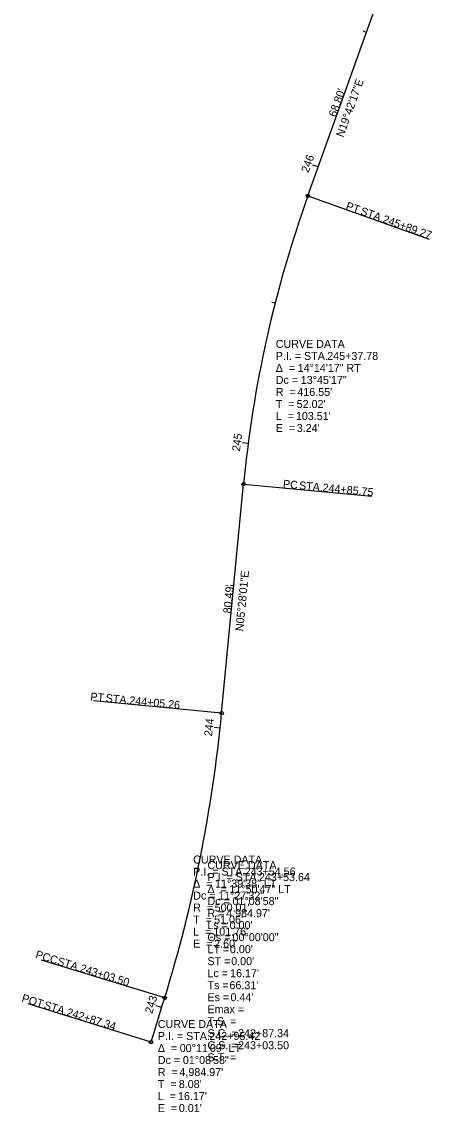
# Model space of a CAD drawing. Extents: x 2479470 to 2480226, y 287083 to 287867.
# Drawn here: x 2479991.5 to 2480134.9, y 287082.9 to 287464.3 of the extents above; entities that cross this region are included whole.
import ezdxf

# ---------------------------------------------------------------- set-up
doc = ezdxf.new("R2010")
doc.units = 0
for name, color, linetype in [('DV_X_Lot_Line', 7, 'Continuous'), ('DV_X_Property_Line', 7, 'Continuous'), ('GE_X_Alignment_100_Cardinal_Points', 7, 'Continuous'), ('GE_X_Alignment_100_Curve_Data', 7, 'Continuous'), ('GE_X_Alignment_100_Distances', 7, 'Continuous'), ('GE_X_Alignment_100_Stations', 7, 'Continuous')]:
    doc.layers.add(name, color=color, linetype=linetype)

msp = doc.modelspace()

# ---------------------------------------------------------------- linework, layer by layer
at = {"layer": 'DV_X_Lot_Line'}
for p, q in [((2480091.52, 287403.39), (2480114.72, 287468.16)), ((2480061.36, 287222.5), (2480069.02, 287302.62))]:
    msp.add_line(p, q, dxfattribs=at)
for centre, radius, start, end in [((2480483.68, 287262.94), 416.55, 160.2952, 174.5332), ((2479563.62, 287270.13), 500.01, 342.8727, 354.5332), ((2475277.55, 288590.94), 4984.97, 342.68688, 342.87268)]:
    msp.add_arc(centre, radius, start, end, dxfattribs=at)
at = {"layer": 'GE_X_Alignment_100_Cardinal_Points'}
for p, q in [((2480091.52, 287403.39), (2480133.89, 287388.22)), ((2480069.02, 287302.62), (2480113.82, 287298.34)), ((2480061.36, 287222.5), (2480016.56, 287226.79)), ((2480041.46, 287122.88), (2479998.45, 287136.14)), ((2480036.67, 287107.44), (2479993.71, 287120.83))]:
    msp.add_line(p, q, dxfattribs=at)
for centre in [(2480091.52, 287403.39), (2480069.02, 287302.62), (2480061.36, 287222.5), (2480041.46, 287122.88), (2480036.67, 287107.44)]:
    msp.add_circle(centre, 0.6, dxfattribs=at)
at = {"layer": 'GE_X_Alignment_100_Stations'}
for p, q in [((2480112, 287460.57), (2480110.87, 287460.97)), ((2480095.14, 287413.5), (2480093.26, 287414.17)), ((2480080.04, 287365.86), (2480078.88, 287366.15)), ((2480070.62, 287316.78), (2480068.64, 287317.04)), ((2480065.62, 287267.04), (2480064.42, 287267.15)), ((2480060.83, 287217.27), (2480058.84, 287217.48)), ((2480053.07, 287167.89), (2480051.89, 287168.14)), ((2480040.42, 287119.54), (2480038.51, 287120.13))]:
    msp.add_line(p, q, dxfattribs=at)

# ---------------------------------------------------------------- texts
at = {"layer": 'DV_X_Property_Line'}
for s, rotation, p in [('N19°42\'17"E', 70.2952, (2480103.89, 287423.69)), ('N05°28\'01"E', 84.5332, (2480068.91, 287251.04))]:
    msp.add_text(s, height=2.8, rotation=rotation, dxfattribs=at).set_placement(p)
at = {"layer": 'GE_X_Alignment_100_Cardinal_Points'}
for s, rotation, p in [('PT', 340.2952, (2480104.54, 287398.77)), (' STA. ', 340.2952, (2480108.64, 287397.3)), ('245+89.27', 340.2952, (2480117.41, 287394.16)), ('PC', 354.5332, (2480082.69, 287301.35)), (' STA. ', 354.5332, (2480087.27, 287300.92)), ('244+85.75', 354.5332, (2480096.55, 287300.03)), ('PT', 354.5332, (2480015.37, 287226.94)), (' STA. ', 354.5332, (2480019.7, 287226.52)), ('244+05.26', 354.5332, (2480028.98, 287225.63)), ('PCC', 342.8727, (2479996.06, 287136.91)), (' STA. ', 342.8727, (2480002.71, 287134.86)), ('243+03.50', 342.8727, (2480011.62, 287132.12)), ('POT', 342.6869, (2479991.23, 287121.65)), (' STA. ', 342.6869, (2479998.03, 287119.53)), ('242+87.34', 342.6869, (2480006.93, 287116.75))]:
    msp.add_text(s, height=2.8, rotation=rotation, dxfattribs=at).set_placement(p)
at = {"layer": 'GE_X_Alignment_100_Curve_Data'}
for s, p in [('CURVE DATA', (2480080.27, 287350.21)), ('P.I. = STA. ', (2480080.27, 287346.01)), ('245+37.78', (2480098.26, 287346.01)), ('Δ  = ', (2480080.27, 287341.81)), ('14°14\'17" RT', (2480087.92, 287341.81)), ('13°45\'17"', (2480089.02, 287337.61)), ('Dc = ', (2480080.27, 287337.61)), ('R  = ', (2480080.27, 287333.41)), ("416.55'", (2480087.81, 287333.41)), ('T  = ', (2480080.27, 287329.21)), ("52.02'", (2480087.59, 287329.21)), ('L  = ', (2480080.27, 287325.01)), ("103.51'", (2480087.31, 287325.01)), ('E  = ', (2480080.27, 287320.81)), ("3.24'", (2480087.62, 287320.81)), ('CURVE DATA', (2480051.41, 287169.89)), ('CURVE DATA', (2480056.4, 287167.94)), ('P.I. = STA. ', (2480051.41, 287165.69)), ('P.I. = STA. ', (2480056.4, 287163.74)), ('243+54.56', (2480069.4, 287165.69)), ('243+53.64', (2480074.39, 287163.74)), ('Δ  = ', (2480051.41, 287161.49)), ('Δ  = ', (2480056.4, 287159.54)), ('11°39\'38" LT', (2480059.05, 287161.49)), ('11°50\'47" LT', (2480064.05, 287159.54)), ('Dc = ', (2480051.41, 287157.29)), ('Dc = ', (2480056.4, 287155.34)), ('11°27\'32"', (2480060.15, 287157.29)), ('01°08\'58"', (2480065.15, 287155.34)), ('R  = ', (2480051.41, 287153.09)), ('R = ', (2480056.4, 287151.14)), ("500.01'", (2480058.94, 287153.09)), ("4,984.97'", (2480062.94, 287151.14)), ('T  = ', (2480051.41, 287148.89)), ("51.06'", (2480058.73, 287148.89)), ("0.00'", (2480064.15, 287146.94)), ('L  = ', (2480051.41, 287144.69)), ('Ls = ', (2480056.4, 287146.94)), ("101.76'", (2480058.44, 287144.69)), ('E  = ', (2480051.41, 287140.49)), ('Θs = ', (2480056.4, 287142.74)), ("2.60'", (2480058.75, 287140.49)), ('00°00\'00"', (2480065.19, 287142.74)), ('LT = ', (2480056.4, 287138.54)), ("0.00'", (2480064.25, 287138.54)), ('ST = ', (2480056.4, 287134.34)), ("0.00'", (2480064.7, 287134.34)), ('Lc = ', (2480056.4, 287130.14)), ("16.17'", (2480064.32, 287130.14)), ('Ts = ', (2480056.4, 287125.94)), ("66.31'", (2480064.09, 287125.94)), ('Es = ', (2480056.4, 287121.74)), ("0.44'", (2480064.46, 287121.74)), ('Emax = ', (2480056.4, 287117.54)), ('T.S. = ', (2480056.4, 287113.34)), ('CURVE DATA', (2480039.06, 287112.36)), ('S.C. = ', (2480056.4, 287109.14)), ('242+87.34', (2480067.11, 287109.14)), ('P.I. = STA. ', (2480039.06, 287108.16)), ('242+95.42', (2480057.05, 287108.16)), ('Δ  = ', (2480039.06, 287103.96)), ('00°11\'09" LT', (2480046.71, 287103.96)), ('C.S. = ', (2480056.4, 287104.94)), ('243+03.50', (2480067.11, 287104.94)), ('Dc = ', (2480039.06, 287099.76)), ('01°08\'58"', (2480047.81, 287099.76)), ('S.T. = ', (2480056.4, 287100.74)), ('R  = ', (2480039.06, 287095.56)), ("4,984.97'", (2480046.6, 287095.56)), ('T  = ', (2480039.06, 287091.36)), ("8.08'", (2480046.38, 287091.36)), ('L  = ', (2480039.06, 287087.16)), ("16.17'", (2480046.1, 287087.16)), ('E  = ', (2480039.06, 287082.96)), ("0.01'", (2480046.41, 287082.96))]:
    msp.add_text(s, height=2.8, dxfattribs=at).set_placement(p)
at = {"layer": 'GE_X_Alignment_100_Distances'}
for s, rotation, p in [("68.80'", 70.2952, (2480101.29, 287430.78)), ("80.49'", 84.5332, (2480064.65, 287257.27))]:
    msp.add_text(s, height=2.8, rotation=rotation, dxfattribs=at).set_placement(p)
at = {"layer": 'GE_X_Alignment_100_Stations'}
for s, rotation, p in [('246', 70.2952, (2480091.69, 287411.28)), ('245', 82.5734, (2480067.73, 287313.92)), ('244', 83.9305, (2480058, 287214.27)), ('243', 72.8324, (2480037.09, 287117.22))]:
    msp.add_text(s, height=2.8, rotation=rotation, dxfattribs=at).set_placement(p)

doc.saveas('drawing.dxf')
